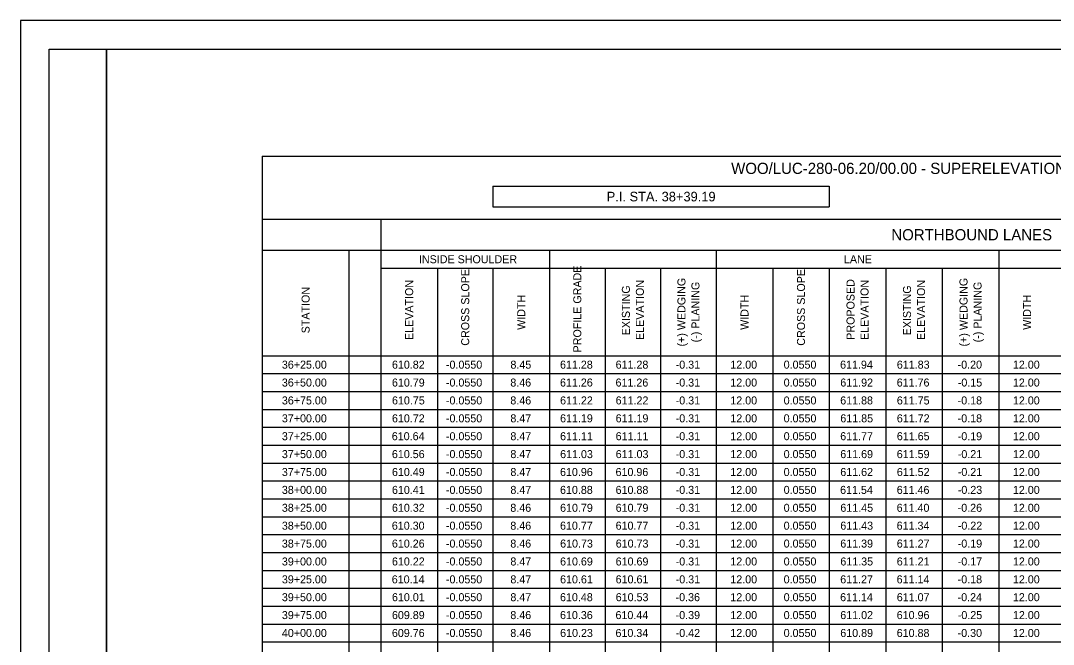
# Model space of a CAD drawing. Extents: x 0 to 34, y 0 to 22.
# Drawn here: x 0 to 18.06, y 11.09 to 22 of the extents above; entities that cross this region are included whole.
import ezdxf

# ---------------------------------------------------------------- set-up
doc = ezdxf.new("R2010")
doc.units = 0
for name, color, linetype in [('Default', 7, 'Continuous'), ('SH_Border', 7, 'Continuous'), ('SH_Cut_Line', 7, 'Continuous')]:
    doc.layers.add(name, color=color, linetype=linetype)

msp = doc.modelspace()

# ---------------------------------------------------------------- linework, layer by layer
at = {"layer": 'Default'}
for p, q in [((4.225, 19.63), (29.277, 19.63)), ((4.225, 19.63), (4.225, 2.369)), ((8.26, 19.103), (14.14, 19.103)), ((8.26, 19.103), (8.26, 18.741)), ((14.14, 19.103), (14.14, 18.741)), ((8.26, 18.741), (14.14, 18.741)), ((4.225, 18.526), (29.277, 18.526)), ((6.3, 18.526), (6.3, 2.369)), ((4.225, 17.983), (29.277, 17.983)), ((5.74, 17.983), (5.74, 2.369)), ((9.249, 17.983), (9.249, 2.369)), ((12.164, 17.983), (12.164, 2.369)), ((17.105, 17.983), (17.105, 2.369)), ((6.3, 17.67), (26.938, 17.67)), ((7.289, 17.67), (7.289, 2.369)), ((8.26, 17.67), (8.26, 2.369)), ((10.22, 17.67), (10.22, 2.369)), ((11.192, 17.67), (11.192, 2.369)), ((13.152, 17.67), (13.152, 2.369)), ((14.14, 17.67), (14.14, 2.369)), ((15.129, 17.67), (15.129, 2.369)), ((16.117, 17.67), (16.117, 2.369)), ((4.225, 16.138), (29.277, 16.138)), ((4.225, 15.825), (29.277, 15.825)), ((4.225, 15.512), (29.277, 15.512)), ((4.225, 15.199), (29.277, 15.199)), ((4.225, 14.886), (29.277, 14.886)), ((4.225, 14.574), (29.277, 14.574)), ((4.225, 14.261), (29.277, 14.261)), ((4.225, 13.948), (29.277, 13.948)), ((4.225, 13.635), (29.277, 13.635)), ((4.225, 13.322), (29.277, 13.322)), ((4.225, 13.009), (29.277, 13.009)), ((4.225, 12.696), (29.277, 12.696)), ((4.225, 12.383), (29.277, 12.383)), ((4.225, 12.07), (29.277, 12.07)), ((4.225, 11.757), (29.277, 11.757)), ((4.225, 11.444), (29.277, 11.444)), ((4.225, 11.131), (29.277, 11.131))]:
    msp.add_line(p, q, dxfattribs=at)
at = {"layer": 'SH_Border'}
for points in [[(0.5, 21.5), (1.5, 21.5), (1.5, 0.5), (0.5, 0.5)], [(1.5, 21.5), (33.5, 21.5), (33.5, 0.5), (1.5, 0.5)]]:
    msp.add_lwpolyline(points, close=True, dxfattribs=at)
at = {"layer": 'SH_Cut_Line'}
msp.add_lwpolyline([(0, 0), (34, 0), (34, 22), (0, 22)], close=True, dxfattribs=at)

# ---------------------------------------------------------------- texts
at = {"layer": 'Default'}
for s, height, p in [('WOO/LUC-280-06.20/00.00 - SUPERELEVATION TABLE', 0.196, (12.425, 19.318)), ('P.I. STA. 38+39.19', 0.168, (10.248, 18.838)), ('NORTHBOUND LANES', 0.196, (15.226, 18.157)), ('INSIDE SHOULDER', 0.14, (6.965, 17.756)), ('LANE', 0.14, (14.397, 17.756)), ('36+25.00', 0.14, (4.568, 15.912)), ('610.82', 0.14, (6.493, 15.912)), ('-0.0550', 0.14, (7.437, 15.912)), ('8.45', 0.14, (8.565, 15.912)), ('611.28', 0.14, (9.432, 15.912)), ('611.28', 0.14, (10.404, 15.912)), ('-0.31', 0.14, (11.455, 15.912)), ('12.00', 0.14, (12.41, 15.912)), ('0.0550', 0.14, (13.343, 15.912)), ('611.94', 0.14, (14.33, 15.912)), ('611.83', 0.14, (15.322, 15.912)), ('-0.20', 0.14, (16.385, 15.912)), ('12.00', 0.14, (17.352, 15.912)), ('36+50.00', 0.14, (4.568, 15.599)), ('610.79', 0.14, (6.493, 15.599)), ('-0.0550', 0.14, (7.437, 15.599)), ('8.46', 0.14, (8.563, 15.599)), ('611.26', 0.14, (9.432, 15.599)), ('611.26', 0.14, (10.403, 15.599)), ('-0.31', 0.14, (11.455, 15.599)), ('12.00', 0.14, (12.41, 15.599)), ('0.0550', 0.14, (13.343, 15.599)), ('611.92', 0.14, (14.333, 15.599)), ('611.76', 0.14, (15.32, 15.599)), ('-0.15', 0.14, (16.388, 15.599)), ('12.00', 0.14, (17.352, 15.599)), ('36+75.00', 0.14, (4.568, 15.286)), ('610.75', 0.14, (6.494, 15.286)), ('-0.0550', 0.14, (7.437, 15.286)), ('8.46', 0.14, (8.563, 15.286)), ('611.22', 0.14, (9.433, 15.286)), ('611.22', 0.14, (10.405, 15.286)), ('-0.31', 0.14, (11.455, 15.286)), ('12.00', 0.14, (12.41, 15.286)), ('0.0550', 0.14, (13.343, 15.286)), ('611.88', 0.14, (14.332, 15.286)), ('611.75', 0.14, (15.322, 15.286)), ('-0.18', 0.14, (16.386, 15.286)), ('12.00', 0.14, (17.352, 15.286)), ('37+00.00', 0.14, (4.568, 14.973)), ('610.72', 0.14, (6.493, 14.973)), ('-0.0550', 0.14, (7.437, 14.973)), ('8.47', 0.14, (8.564, 14.973)), ('611.19', 0.14, (9.433, 14.973)), ('611.19', 0.14, (10.405, 14.973)), ('-0.31', 0.14, (11.455, 14.973)), ('12.00', 0.14, (12.41, 14.973)), ('0.0550', 0.14, (13.343, 14.973)), ('611.85', 0.14, (14.334, 14.973)), ('611.72', 0.14, (15.322, 14.973)), ('-0.18', 0.14, (16.386, 14.973)), ('12.00', 0.14, (17.352, 14.973)), ('37+25.00', 0.14, (4.568, 14.66)), ('610.64', 0.14, (6.49, 14.66)), ('-0.0550', 0.14, (7.437, 14.66)), ('8.47', 0.14, (8.564, 14.66)), ('611.11', 0.14, (9.433, 14.66)), ('611.11', 0.14, (10.405, 14.66)), ('-0.31', 0.14, (11.455, 14.66)), ('12.00', 0.14, (12.41, 14.66)), ('0.0550', 0.14, (13.343, 14.66)), ('611.77', 0.14, (14.332, 14.66)), ('611.65', 0.14, (15.322, 14.66)), ('-0.19', 0.14, (16.387, 14.66)), ('12.00', 0.14, (17.352, 14.66)), ('37+50.00', 0.14, (4.568, 14.347)), ('610.56', 0.14, (6.492, 14.347)), ('-0.0550', 0.14, (7.437, 14.347)), ('8.47', 0.14, (8.564, 14.347)), ('611.03', 0.14, (9.434, 14.347)), ('611.03', 0.14, (10.406, 14.347)), ('-0.31', 0.14, (11.455, 14.347)), ('12.00', 0.14, (12.41, 14.347)), ('0.0550', 0.14, (13.343, 14.347)), ('611.69', 0.14, (14.333, 14.347)), ('611.59', 0.14, (15.321, 14.347)), ('-0.21', 0.14, (16.388, 14.347)), ('12.00', 0.14, (17.352, 14.347)), ('37+75.00', 0.14, (4.568, 14.034)), ('610.49', 0.14, (6.493, 14.034)), ('-0.0550', 0.14, (7.437, 14.034)), ('8.47', 0.14, (8.564, 14.034)), ('610.96', 0.14, (9.432, 14.034)), ('610.96', 0.14, (10.403, 14.034)), ('-0.31', 0.14, (11.455, 14.034)), ('12.00', 0.14, (12.41, 14.034)), ('0.0550', 0.14, (13.343, 14.034)), ('611.62', 0.14, (14.333, 14.034)), ('611.52', 0.14, (15.322, 14.034)), ('-0.21', 0.14, (16.388, 14.034)), ('12.00', 0.14, (17.352, 14.034)), ('38+00.00', 0.14, (4.568, 13.721)), ('610.41', 0.14, (6.493, 13.721)), ('-0.0550', 0.14, (7.437, 13.721)), ('8.47', 0.14, (8.564, 13.721)), ('610.88', 0.14, (9.432, 13.721)), ('610.88', 0.14, (10.404, 13.721)), ('-0.31', 0.14, (11.455, 13.721)), ('12.00', 0.14, (12.41, 13.721)), ('0.0550', 0.14, (13.343, 13.721)), ('611.54', 0.14, (14.33, 13.721)), ('611.46', 0.14, (15.32, 13.721)), ('-0.23', 0.14, (16.388, 13.721)), ('12.00', 0.14, (17.352, 13.721)), ('38+25.00', 0.14, (4.568, 13.408)), ('610.32', 0.14, (6.493, 13.408)), ('-0.0550', 0.14, (7.437, 13.408)), ('8.46', 0.14, (8.563, 13.408)), ('610.79', 0.14, (9.433, 13.408)), ('610.79', 0.14, (10.405, 13.408)), ('-0.31', 0.14, (11.455, 13.408)), ('12.00', 0.14, (12.41, 13.408)), ('0.0550', 0.14, (13.343, 13.408)), ('611.45', 0.14, (14.334, 13.408)), ('611.40', 0.14, (15.319, 13.408)), ('-0.26', 0.14, (16.386, 13.408)), ('12.00', 0.14, (17.352, 13.408)), ('38+50.00', 0.14, (4.568, 13.095)), ('610.30', 0.14, (6.491, 13.095)), ('-0.0550', 0.14, (7.437, 13.095)), ('8.46', 0.14, (8.563, 13.095)), ('610.77', 0.14, (9.432, 13.095)), ('610.77', 0.14, (10.404, 13.095)), ('-0.31', 0.14, (11.455, 13.095)), ('12.00', 0.14, (12.41, 13.095)), ('0.0550', 0.14, (13.343, 13.095)), ('611.43', 0.14, (14.334, 13.095)), ('611.34', 0.14, (15.319, 13.095)), ('-0.22', 0.14, (16.388, 13.095)), ('12.00', 0.14, (17.352, 13.095)), ('38+75.00', 0.14, (4.568, 12.782)), ('610.26', 0.14, (6.492, 12.782)), ('-0.0550', 0.14, (7.437, 12.782)), ('8.46', 0.14, (8.563, 12.782)), ('610.73', 0.14, (9.434, 12.782)), ('610.73', 0.14, (10.406, 12.782)), ('-0.31', 0.14, (11.455, 12.782)), ('12.00', 0.14, (12.41, 12.782)), ('0.0550', 0.14, (13.343, 12.782)), ('611.39', 0.14, (14.333, 12.782)), ('611.27', 0.14, (15.321, 12.782)), ('-0.19', 0.14, (16.387, 12.782)), ('12.00', 0.14, (17.352, 12.782)), ('39+00.00', 0.14, (4.568, 12.469)), ('610.22', 0.14, (6.493, 12.469)), ('-0.0550', 0.14, (7.437, 12.469)), ('8.47', 0.14, (8.564, 12.469)), ('610.69', 0.14, (9.433, 12.469)), ('610.69', 0.14, (10.405, 12.469)), ('-0.31', 0.14, (11.455, 12.469)), ('12.00', 0.14, (12.41, 12.469)), ('0.0550', 0.14, (13.343, 12.469)), ('611.35', 0.14, (14.334, 12.469)), ('611.21', 0.14, (15.321, 12.469)), ('-0.17', 0.14, (16.387, 12.469)), ('12.00', 0.14, (17.352, 12.469)), ('39+25.00', 0.14, (4.568, 12.156)), ('610.14', 0.14, (6.49, 12.156)), ('-0.0550', 0.14, (7.437, 12.156)), ('8.47', 0.14, (8.564, 12.156)), ('610.61', 0.14, (9.433, 12.156)), ('610.61', 0.14, (10.405, 12.156)), ('-0.31', 0.14, (11.455, 12.156)), ('12.00', 0.14, (12.41, 12.156)), ('0.0550', 0.14, (13.343, 12.156)), ('611.27', 0.14, (14.332, 12.156)), ('611.14', 0.14, (15.319, 12.156)), ('-0.18', 0.14, (16.386, 12.156)), ('12.00', 0.14, (17.352, 12.156)), ('39+50.00', 0.14, (4.568, 11.844)), ('610.01', 0.14, (6.493, 11.844)), ('-0.0550', 0.14, (7.437, 11.844)), ('8.47', 0.14, (8.564, 11.844)), ('610.48', 0.14, (9.432, 11.844)), ('610.53', 0.14, (10.406, 11.844)), ('-0.36', 0.14, (11.453, 11.844)), ('12.00', 0.14, (12.41, 11.844)), ('0.0550', 0.14, (13.343, 11.844)), ('611.14', 0.14, (14.33, 11.844)), ('611.07', 0.14, (15.321, 11.844)), ('-0.24', 0.14, (16.385, 11.844)), ('12.00', 0.14, (17.352, 11.844)), ('39+75.00', 0.14, (4.568, 11.531)), ('609.89', 0.14, (6.493, 11.531)), ('-0.0550', 0.14, (7.437, 11.531)), ('8.46', 0.14, (8.563, 11.531)), ('610.36', 0.14, (9.432, 11.531)), ('610.44', 0.14, (10.402, 11.531)), ('-0.39', 0.14, (11.454, 11.531)), ('12.00', 0.14, (12.41, 11.531)), ('0.0550', 0.14, (13.343, 11.531)), ('611.02', 0.14, (14.333, 11.531)), ('610.96', 0.14, (15.32, 11.531)), ('-0.25', 0.14, (16.388, 11.531)), ('12.00', 0.14, (17.352, 11.531)), ('40+00.00', 0.14, (4.568, 11.218)), ('609.76', 0.14, (6.492, 11.218)), ('-0.0550', 0.14, (7.437, 11.218)), ('8.46', 0.14, (8.563, 11.218)), ('610.23', 0.14, (9.434, 11.218)), ('610.34', 0.14, (10.402, 11.218)), ('-0.42', 0.14, (11.455, 11.218)), ('12.00', 0.14, (12.41, 11.218)), ('0.0550', 0.14, (13.343, 11.218)), ('610.89', 0.14, (14.333, 11.218)), ('610.88', 0.14, (15.32, 11.218)), ('-0.30', 0.14, (16.385, 11.218)), ('12.00', 0.14, (17.352, 11.218))]:
    msp.add_text(s, height=height, dxfattribs=at).set_placement(p)
for s, p in [('PROFILE GRADE', (9.804, 16.196)), ('CROSS SLOPE', (7.844, 16.313)), ('CROSS SLOPE', (13.716, 16.313)), ('ELEVATION', (6.864, 16.413)), ('EXISTING ', (10.654, 16.495)), ('ELEVATION', (10.899, 16.413)), ('(+) WEDGING', (11.625, 16.3)), ('(-) PLANING', (11.87, 16.372)), ('PROPOSED ', (14.582, 16.417)), ('ELEVATION', (14.827, 16.413)), ('EXISTING ', (15.57, 16.495)), ('ELEVATION', (15.815, 16.413)), ('(+) WEDGING', (16.558, 16.3)), ('(-) PLANING', (16.803, 16.372)), ('STATION', (5.053, 16.53)), ('WIDTH', (8.824, 16.591)), ('WIDTH', (12.728, 16.591)), ('WIDTH', (17.669, 16.591))]:
    msp.add_text(s, height=0.14, rotation=90, dxfattribs=at).set_placement(p)

doc.saveas('drawing.dxf')
